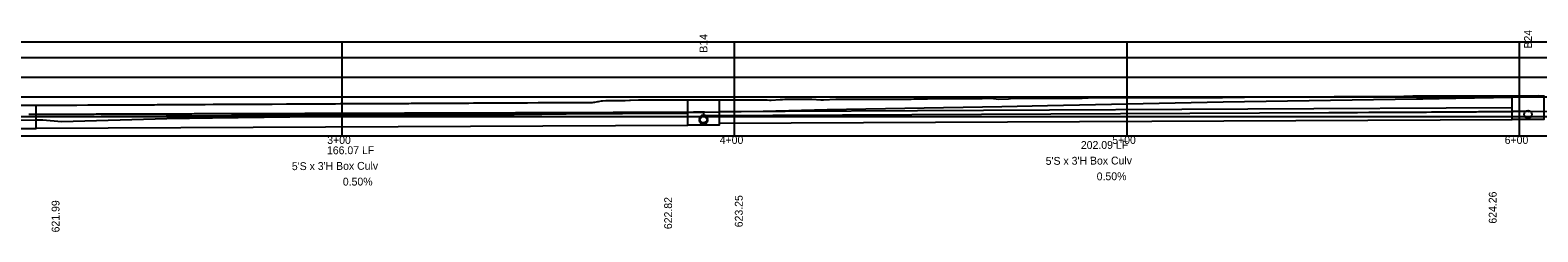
# Model space of a CAD drawing. Extents: x 2253035 to 2279930, y 13774972 to 13793443.
# Drawn here: x 2258605.9 to 2258990, y 13793379.8 to 13793431.2 of the extents above; entities that cross this region are included whole.
import ezdxf

# ---------------------------------------------------------------- set-up
doc = ezdxf.new("R2010")
doc.units = 0
for name, color, linetype in [('Default', 7, 'Continuous'), ('E_Utility_ATT_HH', 7, 'Continuous'), ('E_Utility_ATT_PR_PVC', 7, 'Continuous'), ('E_Utility_Electric_Overhead Electric Power Line_OE_Elevation', 7, 'Continuous'), ('E_Utility_Electric_Overhead Electric Power Line_OE_point', 7, 'Continuous'), ('E_Utillity_Water_Water Line_12in', 7, 'Continuous'), ('E_Utillity_Water_Water Line_1in', 7, 'Continuous'), ('E_Utillity_Water_Water Line_4in', 7, 'Continuous'), ('E_Utillity_Water_Water Line_8in', 7, 'Continuous')]:
    doc.layers.add(name, color=color, linetype=linetype)

msp = doc.modelspace()

# ---------------------------------------------------------------- linework, layer by layer
at = {"layer": 'Default'}
for p, q in [((2258685.4, 13793404.21), (2258685.4, 13793428.21)), ((2258785.4, 13793404.21), (2258785.4, 13793428.21)), ((2258885.4, 13793404.21), (2258885.4, 13793428.21)), ((2258985.4, 13793404.21), (2258985.4, 13793428.21))]:
    msp.add_line(p, q, dxfattribs=at)
at = {"layer": 'E_Utility_ATT_PR_PVC'}
for p, q in [((2258777.45, 13793410.57), (2258777.45, 13793409.41)), ((2258987.54, 13793410.7), (2258987.54, 13793410.47))]:
    msp.add_line(p, q, dxfattribs=at)
for points in [[(2258605.6, 13793409.78), (2258606.15, 13793409.78), (2258606.7, 13793409.78), (2258607.26, 13793409.79), (2258607.81, 13793409.79), (2258608.36, 13793409.79), (2258608.92, 13793409.79), (2258609.47, 13793409.79), (2258610.02, 13793409.8), (2258610.58, 13793409.8), (2258611.13, 13793409.8), (2258611.68, 13793409.8), (2258612.24, 13793409.8), (2258612.79, 13793409.8), (2258613.34, 13793409.81), (2258613.9, 13793409.81), (2258614.45, 13793409.81), (2258615, 13793409.81), (2258615.56, 13793409.81), (2258616.11, 13793409.81), (2258616.66, 13793409.82), (2258617.22, 13793409.82), (2258617.77, 13793409.82), (2258618.32, 13793409.82), (2258618.88, 13793409.82), (2258619.43, 13793409.83), (2258619.98, 13793409.83), (2258620.54, 13793409.83), (2258621.09, 13793409.83), (2258621.64, 13793409.83), (2258622.2, 13793409.83), (2258622.75, 13793409.84), (2258623.3, 13793409.84), (2258623.86, 13793409.84), (2258624.41, 13793409.84), (2258624.96, 13793409.84), (2258625.52, 13793409.84), (2258626.07, 13793409.85), (2258626.62, 13793409.85), (2258627.18, 13793409.85), (2258627.73, 13793409.85), (2258628.28, 13793409.85), (2258628.84, 13793409.86), (2258629.39, 13793409.86), (2258629.94, 13793409.86), (2258630.5, 13793409.86), (2258631.05, 13793409.86), (2258631.6, 13793409.86), (2258632.15, 13793409.87), (2258632.71, 13793409.87), (2258633.26, 13793409.87), (2258633.81, 13793409.87), (2258634.37, 13793409.87), (2258634.92, 13793409.87), (2258635.47, 13793409.88), (2258636.03, 13793409.88), (2258636.58, 13793409.88), (2258637.13, 13793409.88), (2258637.69, 13793409.88), (2258638.24, 13793409.89), (2258638.79, 13793409.89), (2258639.35, 13793409.89), (2258639.9, 13793409.89), (2258640.45, 13793409.89), (2258641.01, 13793409.89), (2258641.56, 13793409.9), (2258642.11, 13793409.9), (2258642.67, 13793409.9), (2258643.22, 13793409.9), (2258643.77, 13793409.9), (2258644.33, 13793409.9), (2258644.88, 13793409.91), (2258645.43, 13793409.91), (2258645.99, 13793409.91), (2258646.54, 13793409.91), (2258647.09, 13793409.91), (2258647.65, 13793409.92), (2258648.2, 13793409.92), (2258648.75, 13793409.92), (2258649.31, 13793409.92), (2258649.86, 13793409.92), (2258650.41, 13793409.92), (2258650.97, 13793409.93), (2258651.52, 13793409.93), (2258652.07, 13793409.93), (2258652.63, 13793409.93), (2258653.18, 13793409.93), (2258653.73, 13793409.93), (2258654.29, 13793409.94), (2258654.84, 13793409.94), (2258655.39, 13793409.94), (2258655.95, 13793409.94), (2258656.5, 13793409.94), (2258657.05, 13793409.95), (2258657.61, 13793409.95), (2258658.16, 13793409.95), (2258658.71, 13793409.95), (2258659.27, 13793409.95), (2258659.82, 13793409.95), (2258660.37, 13793409.96), (2258660.93, 13793409.96), (2258661.48, 13793409.96), (2258662.03, 13793409.96), (2258662.58, 13793409.96), (2258663.14, 13793409.96), (2258663.69, 13793409.97), (2258664.24, 13793409.97), (2258664.8, 13793409.97), (2258665.35, 13793409.97), (2258665.9, 13793409.97), (2258666.46, 13793409.98), (2258667.01, 13793409.98), (2258667.56, 13793409.98), (2258668.12, 13793409.98), (2258668.67, 13793409.98), (2258669.22, 13793409.98), (2258669.78, 13793409.99), (2258670.33, 13793409.99), (2258670.88, 13793409.99), (2258671.44, 13793409.99), (2258671.99, 13793409.99), (2258672.54, 13793409.99), (2258673.1, 13793410), (2258673.65, 13793410), (2258674.2, 13793410), (2258674.76, 13793410), (2258675.31, 13793410), (2258675.86, 13793410.01), (2258676.42, 13793410.01), (2258676.97, 13793410.01), (2258677.52, 13793410.01), (2258678.08, 13793410.01), (2258678.63, 13793410.01), (2258679.18, 13793410.02), (2258679.74, 13793410.02), (2258680.29, 13793410.02), (2258680.84, 13793410.02), (2258681.4, 13793410.02), (2258681.95, 13793410.02), (2258682.5, 13793410.03), (2258683.06, 13793410.03), (2258683.61, 13793410.03), (2258684.16, 13793410.03), (2258684.72, 13793410.03), (2258685.27, 13793410.04), (2258685.82, 13793410.04), (2258686.38, 13793410.04), (2258686.93, 13793410.04), (2258687.48, 13793410.04), (2258688.04, 13793410.04), (2258688.59, 13793410.05), (2258689.14, 13793410.05), (2258689.7, 13793410.05), (2258690.25, 13793410.05), (2258690.8, 13793410.05), (2258691.36, 13793410.05), (2258691.91, 13793410.06), (2258692.46, 13793410.06), (2258693.01, 13793410.06), (2258693.57, 13793410.06), (2258694.12, 13793410.06), (2258694.67, 13793410.07), (2258695.23, 13793410.07), (2258695.78, 13793410.07), (2258696.33, 13793410.07), (2258696.89, 13793410.07), (2258697.44, 13793410.07), (2258697.99, 13793410.08), (2258698.55, 13793410.08), (2258699.1, 13793410.08), (2258699.65, 13793410.08), (2258700.21, 13793410.08), (2258700.76, 13793410.08), (2258701.31, 13793410.09), (2258701.87, 13793410.09), (2258702.42, 13793410.09), (2258702.97, 13793410.09), (2258703.53, 13793410.09), (2258704.08, 13793410.1), (2258704.63, 13793410.1), (2258705.19, 13793410.1), (2258705.74, 13793410.1), (2258706.29, 13793410.1), (2258706.85, 13793410.1), (2258707.4, 13793410.11), (2258707.95, 13793410.11), (2258708.51, 13793410.11), (2258709.06, 13793410.11), (2258709.61, 13793410.11), (2258710.17, 13793410.11), (2258710.72, 13793410.12), (2258711.27, 13793410.12), (2258711.83, 13793410.12), (2258712.38, 13793410.12), (2258712.93, 13793410.12), (2258713.49, 13793410.13), (2258714.04, 13793410.13), (2258714.59, 13793410.13), (2258715.15, 13793410.13), (2258715.7, 13793410.13), (2258716.25, 13793410.13), (2258716.81, 13793410.14), (2258717.36, 13793410.14), (2258717.91, 13793410.14), (2258718.47, 13793410.14), (2258719.02, 13793410.14), (2258719.57, 13793410.14), (2258720.13, 13793410.15), (2258720.68, 13793410.15), (2258721.23, 13793410.15), (2258721.79, 13793410.15), (2258722.34, 13793410.15), (2258722.89, 13793410.16), (2258723.44, 13793410.16), (2258724, 13793410.16), (2258724.55, 13793410.16), (2258725.1, 13793410.16), (2258725.66, 13793410.16), (2258726.21, 13793410.17), (2258726.76, 13793410.17), (2258727.32, 13793410.17), (2258727.87, 13793410.17), (2258728.42, 13793410.17), (2258728.98, 13793410.17), (2258729.53, 13793410.18), (2258730.08, 13793410.18), (2258730.64, 13793410.18), (2258731.19, 13793410.18), (2258731.74, 13793410.18), (2258732.3, 13793410.19), (2258732.85, 13793410.19), (2258733.4, 13793410.19), (2258733.96, 13793410.19), (2258734.51, 13793410.19), (2258735.06, 13793410.19), (2258735.62, 13793410.2), (2258736.17, 13793410.2), (2258736.72, 13793410.2), (2258737.28, 13793410.2), (2258737.83, 13793410.2), (2258738.38, 13793410.2), (2258738.94, 13793410.21), (2258739.49, 13793410.21), (2258740.04, 13793410.21), (2258740.6, 13793410.21), (2258741.15, 13793410.21), (2258741.7, 13793410.22), (2258742.26, 13793410.22), (2258742.81, 13793410.22), (2258743.36, 13793410.22), (2258743.92, 13793410.22), (2258744.47, 13793410.22), (2258745.02, 13793410.23), (2258745.58, 13793410.23), (2258746.13, 13793410.23), (2258746.68, 13793410.23), (2258747.24, 13793410.23), (2258747.79, 13793410.23), (2258748.34, 13793410.24), (2258748.9, 13793410.24), (2258749.45, 13793410.24), (2258750, 13793410.24), (2258750.56, 13793410.24), (2258751.11, 13793410.25), (2258751.66, 13793410.25), (2258752.22, 13793410.25), (2258752.77, 13793410.25), (2258753.32, 13793410.25), (2258753.87, 13793410.25), (2258754.43, 13793410.26), (2258754.98, 13793410.26), (2258755.53, 13793410.26), (2258756.09, 13793410.26), (2258756.64, 13793410.26), (2258757.19, 13793410.26), (2258757.75, 13793410.27), (2258758.3, 13793410.27), (2258758.85, 13793410.27), (2258759.41, 13793410.27), (2258759.96, 13793410.27), (2258760.51, 13793410.28), (2258761.07, 13793410.28), (2258761.62, 13793410.28), (2258762.17, 13793410.28), (2258762.73, 13793410.28), (2258763.28, 13793410.28), (2258763.83, 13793410.29), (2258764.39, 13793410.29), (2258764.94, 13793410.29), (2258765.49, 13793410.29), (2258766.05, 13793410.29), (2258766.6, 13793410.29), (2258767.15, 13793410.3), (2258767.71, 13793410.3), (2258768.26, 13793410.3), (2258768.81, 13793410.3), (2258769.37, 13793410.3), (2258769.92, 13793410.31), (2258770.47, 13793410.31), (2258771.03, 13793410.32), (2258771.58, 13793410.32), (2258772.13, 13793410.33), (2258772.69, 13793410.33), (2258773.24, 13793410.34), (2258773.79, 13793410.34), (2258774.35, 13793410.34), (2258774.9, 13793410.35), (2258775.45, 13793410.35), (2258776.01, 13793410.36), (2258776.56, 13793410.36), (2258777.11, 13793410.37), (2258777.45, 13793410.37), (2258777.45, 13793410.57)], [(2258777.45, 13793409.41), (2258936.79, 13793410.21), (2258940.73, 13793410.23), (2258944.07, 13793410.25), (2258946.97, 13793410.26), (2258949.51, 13793410.27), (2258951.78, 13793410.29), (2258953.83, 13793410.3), (2258955.68, 13793410.31), (2258957.37, 13793410.32), (2258958.93, 13793410.33), (2258960.36, 13793410.34), (2258961.69, 13793410.34), (2258962.93, 13793410.35), (2258964.09, 13793410.36), (2258965.18, 13793410.36), (2258966.2, 13793410.37), (2258967.16, 13793410.38), (2258968.06, 13793410.38), (2258968.92, 13793410.39), (2258969.73, 13793410.39), (2258970.5, 13793410.4), (2258971.23, 13793410.4), (2258971.92, 13793410.4), (2258972.59, 13793410.41), (2258973.22, 13793410.41), (2258973.82, 13793410.42), (2258974.4, 13793410.42), (2258974.95, 13793410.43), (2258975.47, 13793410.43), (2258975.98, 13793410.43), (2258976.46, 13793410.44), (2258976.92, 13793410.44), (2258977.37, 13793410.44), (2258977.79, 13793410.45), (2258978.2, 13793410.45), (2258978.6, 13793410.45), (2258978.98, 13793410.45), (2258979.34, 13793410.46), (2258979.69, 13793410.46), (2258980.03, 13793410.46), (2258980.35, 13793410.47), (2258980.67, 13793410.47), (2258980.97, 13793410.48), (2258981.26, 13793410.48), (2258981.54, 13793410.48), (2258981.81, 13793410.49), (2258982.06, 13793410.49), (2258982.31, 13793410.5), (2258982.56, 13793410.5), (2258982.79, 13793410.5), (2258983.01, 13793410.51), (2258983.23, 13793410.51), (2258983.43, 13793410.51), (2258983.63, 13793410.51), (2258983.83, 13793410.52), (2258984.01, 13793410.52), (2258984.19, 13793410.52), (2258984.36, 13793410.53), (2258984.53, 13793410.53), (2258984.69, 13793410.53), (2258984.84, 13793410.53), (2258984.99, 13793410.54), (2258985.13, 13793410.54), (2258985.27, 13793410.54), (2258985.4, 13793410.54), (2258985.53, 13793410.55), (2258985.65, 13793410.55), (2258985.77, 13793410.55), (2258985.88, 13793410.55), (2258985.99, 13793410.55), (2258986.09, 13793410.56), (2258986.19, 13793410.56), (2258986.28, 13793410.56), (2258986.37, 13793410.56), (2258986.46, 13793410.56), (2258986.54, 13793410.57), (2258986.62, 13793410.57), (2258986.69, 13793410.57), (2258986.76, 13793410.57), (2258986.83, 13793410.57), (2258986.89, 13793410.57), (2258986.95, 13793410.58), (2258987.01, 13793410.58), (2258987.06, 13793410.58), (2258987.11, 13793410.58), (2258987.16, 13793410.58), (2258987.2, 13793410.58), (2258987.24, 13793410.58), (2258987.28, 13793410.59), (2258987.32, 13793410.59), (2258987.35, 13793410.59), (2258987.38, 13793410.59), (2258987.41, 13793410.59), (2258987.43, 13793410.59), (2258987.45, 13793410.59), (2258987.47, 13793410.6), (2258987.49, 13793410.6), (2258987.5, 13793410.6), (2258987.52, 13793410.6), (2258987.53, 13793410.6), (2258987.53, 13793410.6), (2258987.54, 13793410.6), (2258987.54, 13793410.6), (2258987.54, 13793410.6), (2258987.54, 13793410.7)], [(2258987.54, 13793410.47), (2259007.59, 13793410.57)]]:
    msp.add_lwpolyline(points, dxfattribs=at)
at = {"layer": 'E_Utility_Electric_Overhead Electric Power Line_OE_Elevation'}
for p, q in [((2258385.4, 13793424.21), (2259679.58, 13793424.21)), ((2258385.4, 13793419.21), (2259679.58, 13793419.21)), ((2258385.4, 13793414.21), (2259679.58, 13793414.21)), ((2258385.4, 13793409.21), (2259679.58, 13793409.21))]:
    msp.add_line(p, q, dxfattribs=at)
at = {"layer": 'E_Utility_Electric_Overhead Electric Power Line_OE_point'}
msp.add_lwpolyline([(2258385.4, 13793404.21), (2258385.4, 13793428.21), (2259679.58, 13793428.21), (2259679.58, 13793404.21)], close=True, dxfattribs=at)
at = {"layer": 'E_Utillity_Water_Water Line_12in'}
for points in [[(2258599.38, 13793412.09), (2258607.38, 13793412.09), (2258607.38, 13793406.07), (2258599.38, 13793406.07)], [(2258773.45, 13793413.42), (2258781.45, 13793413.42), (2258781.45, 13793407.03), (2258773.45, 13793407.03)], [(2258983.54, 13793414.48), (2258991.54, 13793414.48), (2258991.54, 13793408.47), (2258983.54, 13793408.47)]]:
    msp.add_lwpolyline(points, close=True, dxfattribs=at)
at = {"layer": 'E_Utillity_Water_Water Line_1in'}
msp.add_lwpolyline([(2258603.38, 13793408.29), (2258607.38, 13793408.31), (2258607.38, 13793408.31), (2258609.13, 13793408.33), (2258613.9, 13793407.92), (2258640.71, 13793408.71), (2258652.34, 13793408.89), (2258678.69, 13793409.21), (2258709.8, 13793409.48), (2258722.26, 13793409.64), (2258736.25, 13793409.83), (2258767.36, 13793410.2), (2258773.29, 13793410.27), (2258773.45, 13793410.28), (2258773.45, 13793410.28), (2258777.45, 13793410.34), (2258777.45, 13793410.34), (2258781.45, 13793410.4), (2258781.45, 13793410.4), (2258792.66, 13793410.59), (2258808.96, 13793411), (2258853.5, 13793411.76), (2258865.11, 13793411.97), (2258909.84, 13793412.95), (2258959.16, 13793413.7), (2258960.77, 13793413.73), (2258969.11, 13793413.87), (2258983.54, 13793414.11), (2258983.54, 13793414.11), (2258987.54, 13793414.17), (2258987.54, 13793414.17), (2258991.54, 13793414.24)], dxfattribs=at)
at = {"layer": 'E_Utillity_Water_Water Line_4in'}
for p, q in [((2258607.38, 13793409.2), (2258773.45, 13793410.03)), ((2258781.45, 13793410.46), (2258983.54, 13793411.47)), ((2258781.45, 13793407.46), (2258983.54, 13793408.47)), ((2258607.38, 13793406.2), (2258773.45, 13793407.03))]:
    msp.add_line(p, q, dxfattribs=at)
for centre in [(2258777.45, 13793408.58), (2258777.45, 13793408.16), (2258987.54, 13793409.74)]:
    msp.add_circle(centre, 1, dxfattribs=at)
at = {"layer": 'E_Utillity_Water_Water Line_8in'}
msp.add_lwpolyline([(2258603.69, 13793412.09), (2258606, 13793412.08), (2258607.38, 13793412.07), (2258607.38, 13793412.07), (2258607.53, 13793412.07), (2258608.02, 13793412.07), (2258608.03, 13793412.07), (2258608.04, 13793412.07), (2258608.82, 13793412.08), (2258609.64, 13793412.08), (2258610.03, 13793412.08), (2258610.04, 13793412.08), (2258610.6, 13793412.09), (2258610.89, 13793412.09), (2258610.95, 13793412.09), (2258610.96, 13793412.09), (2258611.01, 13793412.09), (2258612.02, 13793412.09), (2258612.19, 13793412.09), (2258613.46, 13793412.1), (2258613.77, 13793412.1), (2258613.83, 13793412.1), (2258613.87, 13793412.1), (2258614.51, 13793412.11), (2258614.58, 13793412.11), (2258615.55, 13793412.11), (2258616.56, 13793412.12), (2258616.79, 13793412.12), (2258617.19, 13793412.12), (2258617.77, 13793412.12), (2258620.63, 13793412.14), (2258621.5, 13793412.14), (2258622.54, 13793412.15), (2258625.7, 13793412.16), (2258626.4, 13793412.17), (2258627.03, 13793412.17), (2258627.75, 13793412.17), (2258628.22, 13793412.18), (2258632.1, 13793412.2), (2258632.34, 13793412.2), (2258633.4, 13793412.2), (2258633.54, 13793412.2), (2258635.49, 13793412.21), (2258637.49, 13793412.21), (2258637.54, 13793412.21), (2258638.23, 13793412.23), (2258641.75, 13793412.24), (2258642.87, 13793412.25), (2258642.87, 13793412.25), (2258642.88, 13793412.25), (2258643.36, 13793412.25), (2258643.55, 13793412.25), (2258644.83, 13793412.26), (2258644.86, 13793412.26), (2258644.86, 13793412.26), (2258647.54, 13793412.27), (2258649.3, 13793412.28), (2258650.49, 13793412.29), (2258652.54, 13793412.3), (2258654.82, 13793412.31), (2258656.42, 13793412.32), (2258656.65, 13793412.32), (2258657.54, 13793412.33), (2258660.35, 13793412.34), (2258661.43, 13793412.35), (2258661.84, 13793412.35), (2258662.3, 13793412.35), (2258662.98, 13793412.35), (2258666.51, 13793412.37), (2258667.02, 13793412.37), (2258667.54, 13793412.38), (2258671.22, 13793412.4), (2258671.44, 13793412.4), (2258672.4, 13793412.4), (2258673.49, 13793412.41), (2258673.56, 13793412.41), (2258674.55, 13793412.41), (2258678.55, 13793412.43), (2258682.44, 13793412.45), (2258683.68, 13793412.46), (2258684.92, 13793412.47), (2258684.95, 13793412.47), (2258684.95, 13793412.47), (2258687.54, 13793412.48), (2258689.44, 13793412.49), (2258690.58, 13793412.49), (2258690.68, 13793412.5), (2258692.64, 13793412.51), (2258695.18, 13793412.52), (2258696.15, 13793412.52), (2258697.54, 13793412.53), (2258700.46, 13793412.55), (2258701.47, 13793412.55), (2258701.9, 13793412.55), (2258702.37, 13793412.55), (2258703, 13793412.56), (2258706.64, 13793412.58), (2258707.09, 13793412.58), (2258707.86, 13793412.58), (2258708.27, 13793412.59), (2258712.38, 13793412.61), (2258712.46, 13793412.61), (2258713.59, 13793412.61), (2258713.59, 13793412.61), (2258713.62, 13793412.61), (2258717.31, 13793412.61), (2258717.7, 13793412.61), (2258718.87, 13793412.64), (2258722.62, 13793412.66), (2258723.82, 13793412.66), (2258725.01, 13793412.67), (2258725.04, 13793412.67), (2258727.54, 13793412.68), (2258729.49, 13793412.69), (2258731.5, 13793412.7), (2258731.59, 13793412.7), (2258731.7, 13793412.71), (2258732.64, 13793412.71), (2258735.31, 13793412.72), (2258736.23, 13793412.73), (2258737.54, 13793412.73), (2258740.58, 13793412.75), (2258741.51, 13793412.76), (2258741.95, 13793412.76), (2258742.54, 13793412.76), (2258746.04, 13793412.78), (2258746.51, 13793412.78), (2258747.21, 13793412.78), (2258747.52, 13793412.79), (2258749.18, 13793412.79), (2258749.56, 13793412.81), (2258749.68, 13793412.81), (2258749.74, 13793412.81), (2258750.57, 13793412.98), (2258750.63, 13793412.98), (2258750.72, 13793413.01), (2258751.5, 13793413.17), (2258751.71, 13793413.21), (2258751.76, 13793413.22), (2258752.54, 13793413.23), (2258754.53, 13793413.23), (2258755.5, 13793413.27), (2258756.19, 13793413.28), (2258756.55, 13793413.28), (2258757.3, 13793413.28), (2258757.43, 13793413.28), (2258757.54, 13793413.29), (2258758.64, 13793413.39), (2258758.71, 13793413.39), (2258758.75, 13793413.39), (2258758.82, 13793413.39), (2258758.89, 13793413.39), (2258760.86, 13793413.41), (2258762.35, 13793413.41), (2258762.58, 13793413.41), (2258764.78, 13793413.41), (2258764.82, 13793413.41), (2258767.12, 13793413.42), (2258767.63, 13793413.42), (2258769.68, 13793413.42), (2258771.79, 13793413.42), (2258772.57, 13793413.42), (2258773.45, 13793413.42), (2258773.45, 13793413.42), (2258773.46, 13793413.42), (2258775.94, 13793413.42), (2258776.05, 13793413.42), (2258776.19, 13793413.42), (2258777.45, 13793413.42), (2258777.45, 13793413.42), (2258777.54, 13793413.42), (2258777.57, 13793413.42), (2258778.76, 13793413.42), (2258778.94, 13793413.42), (2258781.45, 13793413.42), (2258781.45, 13793413.42), (2258781.52, 13793413.42), (2258782.54, 13793413.42), (2258784.01, 13793413.42), (2258784.18, 13793413.43), (2258786.53, 13793413.43), (2258786.71, 13793413.43), (2258786.86, 13793413.43), (2258787.54, 13793413.43), (2258789.25, 13793413.43), (2258789.63, 13793413.44), (2258791.8, 13793413.44), (2258792.05, 13793413.45), (2258792.2, 13793413.45), (2258792.54, 13793413.45), (2258792.76, 13793413.46), (2258793.71, 13793413.46), (2258794.25, 13793413.35), (2258794.66, 13793413.35), (2258796.99, 13793413.52), (2258797.17, 13793413.52), (2258797.54, 13793413.52), (2258797.57, 13793413.52), (2258798.27, 13793413.61), (2258798.76, 13793413.61), (2258798.77, 13793413.61), (2258802.27, 13793413.61), (2258802.32, 13793413.61), (2258802.54, 13793413.61), (2258802.78, 13793413.61), (2258802.79, 13793413.61), (2258805.06, 13793413.61), (2258807.36, 13793413.42), (2258807.46, 13793413.42), (2258807.54, 13793413.42), (2258808.02, 13793413.44), (2258811.22, 13793413.62), (2258812.61, 13793413.62), (2258814.12, 13793413.62), (2258814.27, 13793413.62), (2258814.39, 13793413.62), (2258816.48, 13793413.62), (2258816.51, 13793413.62), (2258817.54, 13793413.62), (2258817.59, 13793413.62), (2258818.79, 13793413.63), (2258820.97, 13793413.63), (2258821.27, 13793413.63), (2258822.54, 13793413.63), (2258822.75, 13793413.63), (2258824.16, 13793413.63), (2258826.39, 13793413.63), (2258826.73, 13793413.64), (2258826.9, 13793413.64), (2258827.54, 13793413.64), (2258827.86, 13793413.65), (2258828.54, 13793413.65), (2258830.37, 13793413.65), (2258831.08, 13793413.66), (2258832.54, 13793413.67), (2258832.81, 13793413.67), (2258834.52, 13793413.67), (2258836.86, 13793413.78), (2258836.98, 13793413.78), (2258837.04, 13793413.78), (2258837.26, 13793413.78), (2258837.28, 13793413.78), (2258837.54, 13793413.8), (2258837.68, 13793413.81), (2258839.47, 13793413.82), (2258843.13, 13793413.82), (2258845.22, 13793413.82), (2258845.26, 13793413.82), (2258847.44, 13793413.82), (2258847.93, 13793413.82), (2258848.48, 13793413.82), (2258850.7, 13793413.83), (2258852.7, 13793413.65), (2258855.18, 13793413.66), (2258856.3, 13793413.83), (2258856.56, 13793413.83), (2258857.54, 13793413.83), (2258857.91, 13793413.83), (2258859.18, 13793413.83), (2258861.15, 13793413.83), (2258861.32, 13793413.84), (2258862.54, 13793413.84), (2258862.84, 13793413.84), (2258863.77, 13793413.84), (2258865.69, 13793413.84), (2258866.18, 13793413.85), (2258867.54, 13793413.85), (2258869.06, 13793413.85), (2258869.85, 13793413.87), (2258871.66, 13793413.87), (2258872.15, 13793413.88), (2258872.27, 13793413.88), (2258872.54, 13793413.88), (2258873.96, 13793413.88), (2258877.08, 13793414.01), (2258877.33, 13793414.01), (2258877.87, 13793414.02), (2258879.85, 13793414.03), (2258883.21, 13793414.03), (2258883.42, 13793414.03), (2258885.41, 13793414.03), (2258885.45, 13793414.03), (2258885.49, 13793414.03), (2258887.62, 13793414.03), (2258888.09, 13793414.03), (2258889.99, 13793414.03), (2258891.95, 13793414.03), (2258892.68, 13793414.03), (2258894.12, 13793414.03), (2258896.22, 13793414.03), (2258896.57, 13793414.04), (2258897.54, 13793414.04), (2258897.57, 13793414.04), (2258897.78, 13793414.04), (2258899.06, 13793414.04), (2258899.48, 13793414.04), (2258899.59, 13793414.04), (2258899.78, 13793414.04), (2258901.65, 13793414.04), (2258902.38, 13793414.04), (2258902.89, 13793414.04), (2258904.06, 13793414.04), (2258905.17, 13793414.06), (2258905.94, 13793414.06), (2258907.49, 13793414.06), (2258907.54, 13793414.06), (2258907.89, 13793414.07), (2258908.47, 13793414.07), (2258908.75, 13793414.07), (2258909.72, 13793414.07), (2258910.49, 13793414.09), (2258911.53, 13793414.09), (2258911.89, 13793414.1), (2258912.54, 13793414.1), (2258912.78, 13793414.11), (2258913.43, 13793414.11), (2258914.38, 13793414.14), (2258914.72, 13793414.14), (2258915.26, 13793414.14), (2258916.48, 13793414.21), (2258918.04, 13793414.22), (2258918.3, 13793414.22), (2258920.23, 13793414.23), (2258923.5, 13793414.23), (2258923.7, 13793414.23), (2258926.38, 13793414.23), (2258926.42, 13793414.23), (2258927.79, 13793414.23), (2258928.25, 13793414.23), (2258928.77, 13793414.23), (2258931.24, 13793414.24), (2258932.72, 13793414.24), (2258934.12, 13793414.24), (2258936.17, 13793414.24), (2258936.6, 13793414.24), (2258937.54, 13793414.24), (2258938.15, 13793414.25), (2258939.33, 13793414.25), (2258941.15, 13793414.25), (2258941.42, 13793414.25), (2258942.54, 13793414.25), (2258943.02, 13793414.26), (2258943.86, 13793414.26), (2258945.59, 13793414.26), (2258946.35, 13793414.27), (2258947.54, 13793414.27), (2258948.87, 13793414.27), (2258950.07, 13793414.3), (2258951.53, 13793414.3), (2258952.25, 13793414.32), (2258952.34, 13793414.32), (2258952.54, 13793414.32), (2258952.72, 13793414.32), (2258953.83, 13793414.32), (2258955.89, 13793414.41), (2258958.23, 13793414.42), (2258958.74, 13793414.43), (2258960.61, 13793414.44), (2258963.79, 13793414.44), (2258963.99, 13793414.44), (2258965.87, 13793414.44), (2258965.91, 13793414.44), (2258965.95, 13793414.44), (2258967.96, 13793414.44), (2258968.41, 13793414.44), (2258970.21, 13793414.44), (2258972.07, 13793414.44), (2258972.76, 13793414.44), (2258973.54, 13793414.44), (2258975.73, 13793414.44), (2258976.26, 13793414.45), (2258976.38, 13793414.45), (2258977.54, 13793414.45), (2258977.69, 13793414.45), (2258978.71, 13793414.45), (2258979.62, 13793414.46), (2258981.72, 13793414.46), (2258982.54, 13793414.46), (2258983.11, 13793414.47), (2258983.54, 13793414.47), (2258983.54, 13793414.47), (2258984.26, 13793414.47), (2258986.08, 13793414.47), (2258986.92, 13793414.48), (2258987.05, 13793414.48), (2258987.54, 13793414.48), (2258987.54, 13793414.48), (2258987.54, 13793414.48), (2258988.79, 13793414.48), (2258990.15, 13793414.51)], dxfattribs=at)

# ---------------------------------------------------------------- texts
at = {"layer": 'Default'}
for s, p in [('3+00', (2258681.59, 13793402.21)), ('4+00', (2258781.59, 13793402.21)), ('5+00', (2258881.59, 13793402.21)), ('6+00', (2258981.59, 13793402.21))]:
    msp.add_text(s, height=2, dxfattribs=at).set_placement(p)
at = {"layer": 'E_Utility_ATT_HH'}
for s, rotation, p in [('B24', 90, (2258988.54, 13793426.51)), ('B14', 90, (2258778.45, 13793425.45)), ('166.07 LF', 0.2865, (2258681.53, 13793399.57)), ('202.09 LF', 0.2865, (2258873.61, 13793400.92)), ("5'S x 3'H Box Culv", 0.2865, (2258672.58, 13793395.53)), ("5'S x 3'H Box Culv", 0.2865, (2258864.66, 13793396.88)), ('0.50%', 0.2865, (2258685.57, 13793391.59)), ('0.50%', 0.2865, (2258877.65, 13793392.94)), ('623.25', 90, (2258787.45, 13793380.98)), ('624.26', 90, (2258979.54, 13793381.89)), ('621.99', 90, (2258613.38, 13793379.67)), ('622.82', 90, (2258769.45, 13793380.5))]:
    msp.add_text(s, height=2, rotation=rotation, dxfattribs=at).set_placement(p)

doc.saveas('drawing.dxf')
